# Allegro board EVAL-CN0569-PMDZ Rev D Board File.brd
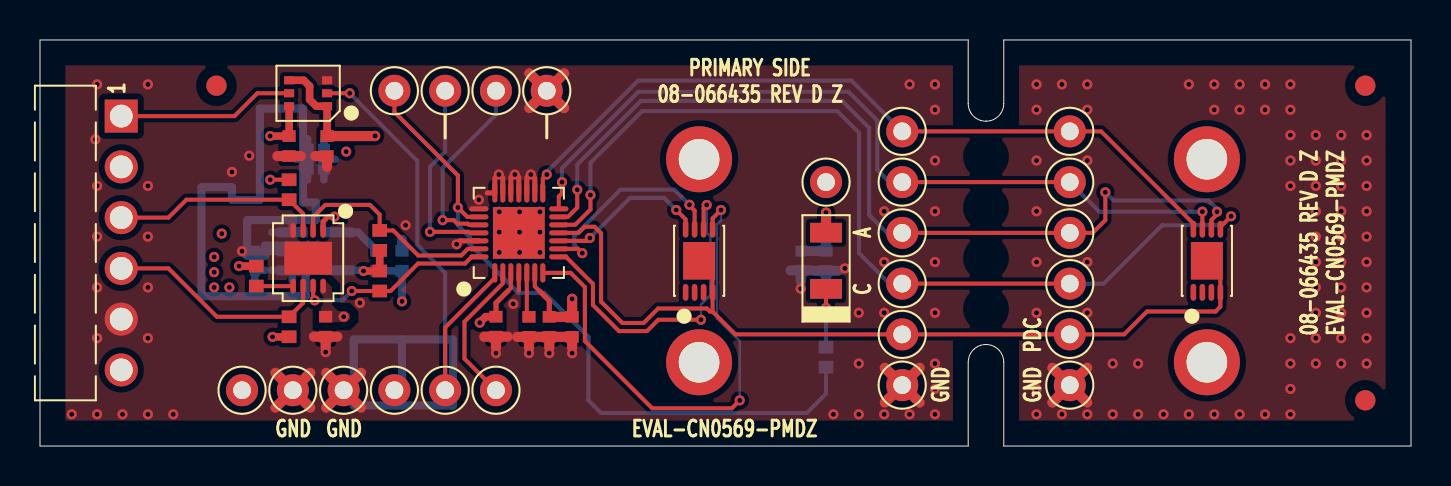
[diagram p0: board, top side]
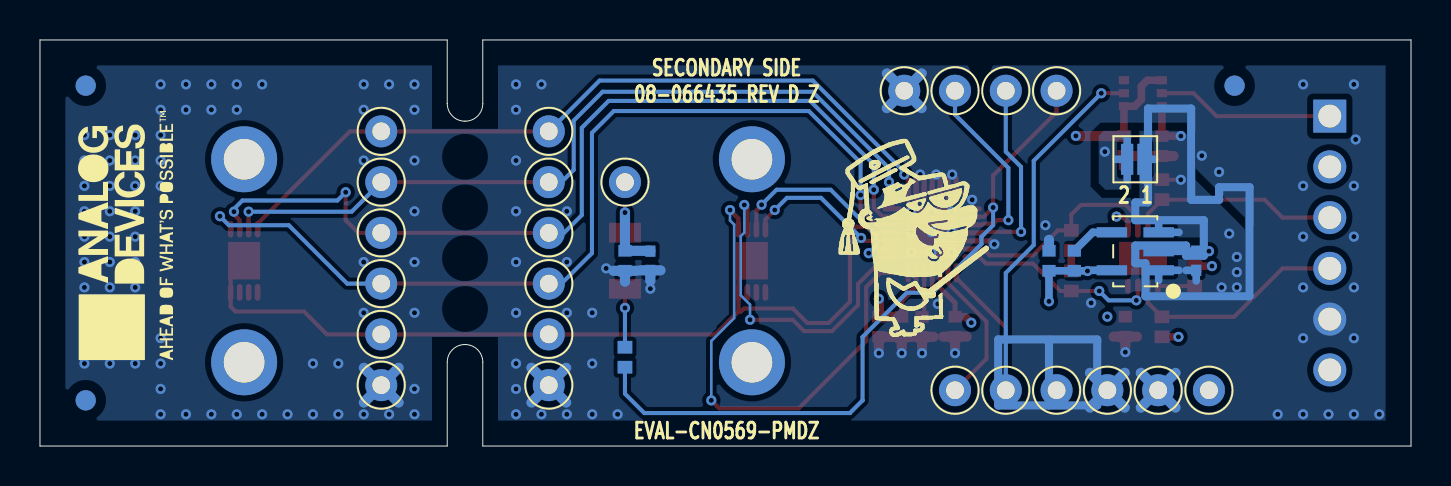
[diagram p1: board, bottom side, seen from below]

Outline 68.58 x 20.32 mm; copper layers: TOP, L2_GND, L3_PWR, BOTTOM. Coordinates in mm from the lower left corner of the outline.
Outline path: 0,20.32 0,0 46.43,0 46.43,4.19 arc(46.69,4.82) 47.32,5.08 47.32,5.08 arc(47.95,4.82) 48.21,4.19 48.21,0 68.58,0 68.58,20.32 48.21,20.32 48.21,17.14 arc(47.95,16.51) 47.32,16.25 47.31,16.25 arc(46.69,16.51) 46.43,17.14 46.43,20.32 0,20.32

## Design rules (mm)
constraint set DEFAULT: min track width 0.203

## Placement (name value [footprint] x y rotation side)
AGND  TP_VIA  [TPC63D35]  12.65 2.79 0 top
C1  1uF  [C0402]  24.46 5.96 270 top
C2  10uF  [C0402]  25.48 5.96 270 top
C3  0.1uF  [C0402]  26.62 5.96 270 top
C4  0.1uF  [C0402]  22.81 5.97 270 top
C5  0.1uF  [C0402]  12.46 15.01 270 top
C6  0.1uF  [C0402]  14.36 15.01 270 top
C7  0.01uF  [C0402]  14.29 5.97 270 top
C8  1uF  [C0402H22]  10.74 9.27 90 bottom
C9  0.01uF  [C0402]  16.84 9.27 90 bottom
C10  10uF  [C0402]  18.11 9.27 90 bottom
C11  2.2uF  [C0402H22]  38.05 9.27 270 bottom
C12  10uF  [C0402]  39.32 9.27 270 bottom
DGND  TP_VIA  [TPC63D35]  15.19 2.79 0 top
GND  TP_VIA  [TPC63D35]  25.35 17.78 0 top
GND1  TP_VIA  [TPC63D35]  43.13 3.05 0 top
GND2  TP_VIA  [TPC63D35]  51.51 3.05 0 top
IO0  TP_VIA  [TPC63D35]  20.27 2.79 0 top
IO1  TP_VIA  [TPC63D35]  22.81 2.79 0 top
IR_LED  SFH 4056  [LED1206H47]  39.32 9.27 90 top
JP1  -  [JPSLD02]  13.79 14.35 0 bottom
LED1  TP_VIA  [TPC63D35]  17.73 17.78 90 top
LED2  TP_VIA  [TPC63D35]  20.27 17.78 0 top
LED3  TP_VIA  [TPC63D35]  22.81 17.78 0 top
NOREF  -  []  0 0 0 top
NOREF#2  -  []  48.21 0 0 top
NOREF#3  -  [unnamed#2]  32.97 14.35 0 top
NOREF#4  -  []  276.81 307.21 0 top
NOREF#5  -  []  94.82 -25.4 270 top
NOREF#6  -  []  46.73 6.19 0 top
NOREF#7  -  []  -104.19 -156.34 0 top
NOREF#8  -  []  -104.19 -156.34 0 top
NOREF#9  -  []  0 0 0 top
NOREF#10  -  []  -43.23 214.5 0 top
NOREF#11  -  []  0 20.32 270 top
NOREF#12  -  []  13.79 14.61 0 top
NOREF#13  -  []  246.38 6.22 0 top
NOREF#14  -  []  0 20.32 0 top
NOREF#15  -  []  68.58 0 90 top
NOREF#16  -  [unnamed#2]  8.83 18.03 0 top
NOREF#17  -  []  46.43 0 0 top
NOREF#18  -  [unnamed#2]  66.29 18.03 0 top
NOREF#19  -  []  -104.19 -156.34 0 top
NOREF#20  -  [unnamed#2]  32.97 4.19 0 top
NOREF#21  -  []  -53.39 -14.1 0 top
NOREF#22  -  []  -66.09 170.05 0 top
NOREF#23  -  []  47.31 17.89 0 top
NOREF#24  -  []  0 0 0 top
NOREF#25  -  []  -104.19 -156.34 0 top
NOREF#26  -  [unnamed#2]  66.29 2.29 0 top
NOREF#27  -  []  68.58 20.32 180 top
NOREF#28  -  []  68.58 0 90 top
NOREF#29  -  [unnamed#2]  58.37 14.35 0 top
NOREF#30  -  []  68.58 0 0 top
NOREF#31  -  [unnamed#2]  58.37 4.19 0 top
NOREF#32  -  []  0 20.32 0 top
NOREF#33  -  []  72.9 10.16 90 bottom
NOREF#34  -  [unnamed#2]  66.29 18.03 180 bottom
NOREF#35  -  [unnamed#2]  8.83 18.03 180 bottom
NOREF#36  -  [unnamed#2]  66.29 2.29 180 bottom
P1  TSW-106-25-F-S-RA  [CNHDRRA1X6H122]  4.06 16.51 270 top
PD5  TP_VIA  [TPC63D35]  43.13 8.13 0 top
PD6  TP_VIA  [TPC63D35]  43.13 10.67 0 top
PD7  TP_VIA  [TPC63D35]  43.13 13.21 0 top
PD8  TP_VIA  [TPC63D35]  43.13 15.75 0 top
PDC  TP_VIA  [TPC63D35]  43.13 5.59 0 top
PDC2  TP_VIA  [TPC63D35]  51.51 5.59 0 top
R1  0  [R0402]  39.32 4.44 270 bottom
R2  10K  [R0402]  12.46 5.97 90 top
R3  10K  [R0402]  12.46 12.83 270 top
R4  10K  [R0402]  10.82 8.5 270 top
R5  10K  [R0402]  16.99 8.26 270 top
R6  10K  [R0402]  16.99 10.29 90 top
U1  ADPD2140BCPZN-R7  [DFN8_2X3_PAD1_59X1_89]  32.97 9.27 0 top
U2  ADPD2140BCPZN-R7  [DFN8_2X3_PAD1_59X1_89]  58.37 9.27 0 top
U3  ADPD1080BCPZ  [QFN28_4X4_PAD2_6X2_6]  23.95 10.67 0 top
U4  ADG3301BKSZ  [SC70-6]  13.41 17.65 90 top
U5  LTC4313IDD-3#PBF  [DFN8_3X3_PAD2_38X1_65]  13.41 9.4 180 top
U6  LT1761ES5-1.8#TRPBF  [TSOT-5]  13.79 9.74 90 bottom
UNK1V8  TP_VIA  [TPC63D35]  17.73 2.79 0 top
VCC  TP_VIA  [TPC63D35]  10.11 2.79 0 top
VLED  TP_VIA  [TPC63D35]  39.32 13.21 0 top
XL2  TP_VIA  [TPC63D35]  51.51 10.67 0 top
XR2  TP_VIA  [TPC63D35]  51.51 8.13 0 top
YB2  TP_VIA  [TPC63D35]  51.51 13.21 0 top
YT2  TP_VIA  [TPC63D35]  51.51 15.75 0 top

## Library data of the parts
AGND DGND GND GND1 GND2 IO0 IO1 LED1-LED3 PD5-PD8 PDC PDC2 UNK1V8 VCC VLED XL2 XR2 YB2 YT2 = NCTESTPAD: Tolerance: N/A; User Part Number: UPN; alternate symbols: (); part number: NCTESTPAD_TH-TP_VIA,E012149,TPC63D35; tolerance: N/A
C1 = CAP: User Part Number: UPN; Tolerance: 20; alternate symbols: (C0402L); part number: CAP_SM-1UF,16V,20,E020695,C0402; tolerance: 20
C2 C10 C12 = CAP: User Part Number: UPN; Tolerance: 20; alternate symbols: (C0402L); part number: CAP_SM-10UF,6.3V,20,E032074,C0402; tolerance: 20
C3-C6 = CAP: User Part Number: UPN; Tolerance: 10; alternate symbols: (C0402L_ALT,C0402L); part number: CAP_SM-0.1UF,25V,10,E025798,C0402; tolerance: 10
C7 C9 = CAP: User Part Number: UPN; Tolerance: 10; alternate symbols: (C0402L); part number: CAP_SM-0.01UF,50V,10,E021852,C0402; tolerance: 10
C8 = CAP: Tolerance: 20; User Part Number: UPN; alternate symbols: (); part number: CAP_SM-1UF,25V,20,E028570,C0402H22; tolerance: 20
C11 = CAP: Tolerance: 10; User Part Number: UPN; alternate symbols: (); part number: CAP_SM-2.2UF,10V,10,E027484,C0402H22; tolerance: 10
IR_LED = DIOLED: Tolerance: N/A; User Part Number: UPN; alternate symbols: (); part number: DIOLED_SM-SFH 4056,1.6V,N/A,E031632,LED1206H47; tolerance: N/A
JP1 = NC2P: User Part Number: UPN; Tolerance: N/A; alternate symbols: (); part number: NC2P_SM-JPSLD02,E006230,JPSLD02; tolerance: N/A
P1 = CN6P: User Part Number: UPN; Tolerance: N/A; alternate symbols: (); part number: CN6P_TH-TSW-106-25-F-S-RA,E018547,CNHDRRA1X6H122; tolerance: N/A
R1 = RES: User Part Number: UPN; Tolerance: JUMPER; alternate symbols: (R0402L,R0402L_ALT); part number: RES_SM-0,E003438,1/10W,JUMPER,R0402; tolerance: JUMPER
R2-R6 = RES: User Part Number: UPN; Tolerance: 1; alternate symbols: (R0402L,R0402L_ALT); part number: RES_SM-10K,E003751,1/10W,1,R0402; tolerance: 1
U1 U2 = ADPD2140: Tolerance: N/A; User Part Number: UPN; alternate symbols: (); part number: ADPD2140_SM-ADPD2140BCPZN-R7,E032570,DFN8_2X3_PAD1_59X1_89; tolerance: N/A
U3 = ADPD1080_V2: Tolerance: N/A; User Part Number: UPN; alternate symbols: (); part number: ADPD1080_V2_SM-ADPD1080BCPZ,E030400,QFN28_4X4_PAD2_6X2_6; tolerance: N/A
U4 = ADG3301: Tolerance: N/A; User Part Number: UPN; alternate symbols: (); part number: ADG3301_SM-ADG3301BKSZ,E010847,SC70-6; tolerance: N/A
U5 = LINLTC4313: User Part Number: UPN; Tolerance: N/A; alternate symbols: (); part number: LINLTC4313_SM-LTC4313IDD-3#PBF,E034872,DFN8_3X3_PAD2_38X1_65; tolerance: N/A
U6 = LINLT1761_X: User Part Number: UPN; Tolerance: N/A; alternate symbols: (); part number: LINLT1761_X_SM-LT1761ES5-1.8#TRPBF,E015635,TSOT-5; tolerance: N/A

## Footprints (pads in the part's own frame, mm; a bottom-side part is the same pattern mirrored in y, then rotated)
C0402
  rect 0.584x0.66 smd: 1(-0.5,0) 2(0.5,0)
C0402H22
  rect 0.559x0.508 smd: 1(-0.479,0) 2(0.479,0)
CNHDRRA1X6H122
  rect 1.651x1.651 hole 1.143: 1(0,0)
  round 1.651 hole 1.143: 2(2.54,0) 3(5.08,0) 4(7.62,0) 5(10.16,0) 6(12.7,0)
DFN8_2X3_PAD1_59X1_89
  oval 0.279x0.838 smd: 1(-0.675,-1.581) 2(-0.225,-1.581) 3(0.225,-1.581) 4(0.675,-1.581) 5(0.675,1.581) 6(0.225,1.581) 7(-0.225,1.581) 8(-0.675,1.581)
  rect 1.6x1.88 smd: PAD(0,0)
DFN8_3X3_PAD2_38X1_65
  oval 0.279x0.737 smd: 1(-0.75,-1.393) 2(-0.25,-1.393) 3(0.25,-1.393) 4(0.75,-1.393) 5(0.75,1.393) 6(0.25,1.393) 7(-0.25,1.393) 8(-0.75,1.393)
  rect 2.388x1.651 smd: PAD(0,0)
JPSLD02
  rect 0.61x1.549 smd: 1(-0.406,0) 2(0.406,0)
LED1206H47
  rect 0.991x1.6 smd: A(1.405,0) C(-1.405,0)
QFN28_4X4_PAD2_6X2_6
  oval 0.254x0.965 smd: 1(-1.2,-2) 2(-0.8,-2) 3(-0.4,-2) 4(0,-2) 5(0.4,-2) 6(0.8,-2) 7(1.2,-2) 15(1.2,2) 16(0.8,2) 17(0.4,2) 18(0,2) 19(-0.4,2) 20(-0.8,2) 21(-1.2,2)
  oval 0.965x0.254 smd: 8(2,-1.2) 9(2,-0.8) 10(2,-0.4) 11(2,0) 12(2,0.4) 13(2,0.8) 14(2,1.2) 22(-2,1.2) 23(-2,0.8) 24(-2,0.4) 25(-2,0) 26(-2,-0.4) 27(-2,-0.8) 28(-2,-1.2)
  rect 2.591x2.591 smd: PAD(0,0)
R0402
  rect 0.635x0.737 smd: 1(-0.5,0) 2(0.5,0)
SC70-6
  rect 0.406x0.508 smd: 1(-0.65,-0.95) 2(0,-0.95) 3(0.65,-0.95) 4(0.65,0.95) 5(0,0.95) 6(-0.65,0.95)
TPC63D35
  round 1.6 hole 0.889: 1(0,0)
TSOT-5
  rect 0.508x1.524 smd: 1(-0.95,-1.17) 2(0,-1.17) 3(0.95,-1.17) 4(0.95,1.17) 5(-0.95,1.17)
unnamed#2
  round 3.302 hole 2.032 unplated: (0,0)

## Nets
1V8_SCL: R6.2(N2) U3.27 U5.2
1V8_SDA: R5.2(N2) U3.28 U5.7
1V8_VDD: C2.1 C3.1 C4.1 C6.1 C9.1 C10.1 R4.1 R5.1 R6.1 U3.3 U3.6 U4.1 U4.4 U6.5 UNK1V8.1
GND: AGND.1(N1) C1.2(N2) C2.2(N2) C3.2(N2) C4.2(N2) C5.2(N2) C6.2(N2) C7.2(N2) C8.2(N2) C10.2(N2) C11.2(N2) C12.2(N2) DGND.1(N1) GND.1(N1) GND1.1(N1) GND2.1(N1) P1.5 U3.4 U3.16 U3.17 U3.18 U3.19 U3.20 U3.21 U3.22 U3.26 U3.PAD U4.3 U5.4 U5.PAD U6.2
IO0: IO0.1(N1) U3.1 U4.2
PD5: PD5.1(N1) U2.5 U3.12 XR2.1(N1)
PD6: PD6.1(N1) U2.6 U3.13 XL2.1(N1)
PD7: PD7.1(N1) U2.7 U3.14 YB2.1(N1)
PD8: PD8.1(N1) U2.8(YT) U3.15 YT2.1(N1)
PDC: PDC.1(N1) PDC2.1(N1) U1.4 U1.PAD U2.4 U2.PAD U3.11
PMOD_VCC: C5.1 C7.1 C8.1 JP1.1 P1.6(N6) R2.1 R3.1 U4.6 U5.1 U5.8(VCC) U6.1 U6.3(SHDN_N) VCC.1(N1)
UNNAMED_2_ADPD1080V2_I3_GPIO1: IO1.1(N1) U3.2
UNNAMED_2_ADPD1080V2_I3_LEDX1: LED1.1(N1) R1.2(N2) U3.23
UNNAMED_2_ADPD1080V2_I3_LEDX2: LED2.1(N1) U3.25
UNNAMED_2_ADPD1080V2_I3_LEDX3: LED3.1(N1) U3.24
UNNAMED_2_ADPD1080V2_I3_PD1: U1.5 U3.7
UNNAMED_2_ADPD1080V2_I3_PD2: U1.6 U3.8
UNNAMED_2_ADPD1080V2_I3_PD3: U1.7 U3.9
UNNAMED_2_ADPD1080V2_I3_PD4: U1.8(YT) U3.10
UNNAMED_2_ADPD1080V2_I3_VREF: C1.1 U3.5(VREF)
UNNAMED_2_DIOLED_I122_N: IR_LED.C R1.1
UNNAMED_3_ADG3301_I41_Y: P1.1 U4.5(Y)
UNNAMED_3_CAP_I23_N2: C9.2(N2) U6.4
UNNAMED_3_LINLTC4313_I1_READY: R4.2(N2) U5.5
UNNAMED_3_LINLTC4313_I1_SCLIN: P1.3 R3.2(N2) U5.3
UNNAMED_3_LINLTC4313_I1_SDAIN: P1.4 R2.2(N2) U5.6
VLED: C11.1 C12.1 IR_LED.A(P) JP1.2(N2) VLED.1(N1)

Pads without a net: P1 2; U1 1 2 3; U2 1 2 3

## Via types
v1: diameter 0.508, hole 0.254, TOP to BOTTOM, 174 vias

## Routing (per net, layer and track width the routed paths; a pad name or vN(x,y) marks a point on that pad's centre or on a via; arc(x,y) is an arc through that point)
1V8_SCL: length 10.9
  TOP w0.203: U5.2 13.66,11.45 14.27,12.06 16.51,12.06 16.99,11.58 R6.2 17.67,10.79 18.92,9.54 21.07,9.54 21.4,9.87 U3.27
1V8_SDA: length 9.9
  TOP w0.203: v1(15.6,7.76) R5.2 17.54,7.76 18.91,9.13 21.26,9.13 21.6,9.47 U3.28 ; v1(13.74,7.29) 13.66,7.37 U5.7
  BOTTOM w0.203: v1(13.74,7.29) 15.13,7.29 v1(15.6,7.76)
1V8_VDD: length 30.2
  TOP w0.203: 24.99,7.75 24.75,7.99 U3.6 ; 23.42,7.77 23.55,7.91 U3.3
  TOP w0.254: C2.1 25.48,7.26 24.99,7.75 ; 23.42,7.77 22.81,7.16 C4.1
  TOP w0.381: R4.1 v1(9.96,9) ; C4.1 22.3,6.47 v1(22,6.17) ; C6.1 U4.1 13.82,17 13.49,17.34 13.49,18.01 13.19,18.3 U4.4 ; v1(16.18,8.76) R5.1 R6.1
  TOP w0.508: C6.1 16.76,15.51 v1(16.76,15.52) ; v1(26.62,7.37) C3.1 C2.1
  L3_PWR w0.508: 16.76,9.85 v1(16.76,15.52)
  L3_PWR w0.711: 18.6,3.66 UNK1V8.1 16.86,3.66
  BOTTOM w0.381: U6.5 16.15,8.8 v1(16.18,8.76) 16.2,8.77 C9.1 C10.1 v1(18.11,7.24)
GND: length 114.4
  TOP w0.203: 23.95,7.77 U3.4
  TOP w0.254: v1(20.84,10.1) 21.01,10.27 U3.26 ; U3.18 23.95,13.46 ; 22.37,12.67 U3.21 22.75,13.4 ; U3.16 24.75,13.42 ; 23.55,13.46 U3.19 ; U3.20 23.15,13.42 ; U3.17 24.35,13.44
  TOP w0.508: GND.1 26.22,18.65 ; GND.1 24.48,16.91 ; GND.1 26.22,16.91 ; GND.1 24.48,18.65 ; AGND.1 13.52,1.92 ; AGND.1 11.78,3.66 ; AGND.1 13.52,3.66 ; AGND.1 11.78,1.92 ; GND2.1 52.38,3.92 ; GND2.1 52.38,2.18 ; GND2.1 50.64,2.18 ; GND2.1 50.64,3.92 ; 14.32,3.66 DGND.1 ; DGND.1 16.06,3.66 ; DGND.1 14.32,1.92 ; DGND.1 16.06,1.92 ; 42.26,2.18 GND1.1 ; GND1.1 44,3.92 ; GND1.1 42.26,3.92 ; GND1.1 44,2.18 ; 13.78,14.51 C6.2 14.36,13.96 ; 24.46,4.92 C1.2 ; C1.2 23.88,5.46 ; C1.2 C2.2 ; 11.88,14.51 C5.2 13.05,14.51 ; C7.2 14.88,5.47 ; C7.2 13.71,5.47 ; C7.2 14.29,4.93 ; 25.48,4.92 C2.2 ; C2.2 C3.2 26.62,4.92 ; C4.2 23.39,5.47 ; C4.2 22.81,4.93 ; C4.2 22.22,5.47
  L2_GND w0.711: 50.64,3.92 GND2.1 ; GND2.1 52.38,3.92 ; GND2.1 52.38,2.18 ; GND2.1 50.64,2.18 ; 24.48,18.65 GND.1 ; GND.1 26.22,18.65 ; GND.1 24.48,16.91 ; GND.1 26.22,16.91 ; 14.32,3.66 DGND.1 ; DGND.1 16.06,1.92 ; DGND.1 14.32,1.92 ; DGND.1 16.06,3.66 ; GND1.1 44,3.92 ; GND1.1 42.26,2.18 ; GND1.1 42.26,3.92 ; GND1.1 44,2.18 ; 11.78,3.66 AGND.1 ; AGND.1 11.78,1.92 ; AGND.1 13.52,3.66 ; AGND.1 13.52,1.92
  L3_PWR w0.711: AGND.1 13.52,3.66 ; AGND.1 11.78,3.66 ; AGND.1 13.52,1.92 ; AGND.1 11.78,1.92 ; GND2.1 52.38,2.18 ; GND2.1 52.38,3.92 ; GND2.1 50.64,3.92 ; GND2.1 50.64,2.18 ; 42.26,2.18 GND1.1 ; GND1.1 44,2.18 ; GND1.1 42.26,3.92 ; GND1.1 44,3.92 ; 14.32,3.66 DGND.1 14.32,1.92
  BOTTOM w0.381: U6.2 11.4,9.74 11.39,9.75 C8.2 v1(10.1,9.75)
  BOTTOM w0.508: AGND.1 13.52,1.92 ; AGND.1 13.52,3.66 ; AGND.1 11.78,1.92 ; AGND.1 11.78,3.66 ; 14.32,1.92 DGND.1 ; DGND.1 16.06,1.92 ; DGND.1 14.32,3.66 ; DGND.1 16.06,3.66 ; 50.64,2.18 GND2.1 ; GND2.1 52.38,3.92 ; GND2.1 50.64,3.92 ; GND2.1 52.38,2.18 ; 42.26,3.92 GND1.1 ; GND1.1 44,2.18 ; GND1.1 42.26,2.18 ; GND1.1 44,3.92 ; 38.73,8.77 C12.2 ; C12.2 39.32,8.22 ; C12.2 39.9,8.77 ; C10.2 18.11,10.32 ; GND.1 26.22,18.65 ; GND.1 26.22,16.91 ; GND.1 24.48,18.65 ; GND.1 24.48,16.91 ; C11.2 38.56,8.79 ; C11.2 38.05,8.26 ; C11.2 37.54,8.79
  vias: v1(1.59,1.59) v1(2.77,15.34) v1(2.86,18.1) v1(2.86,13.02) v1(2.86,10.48) v1(2.86,7.94) v1(2.86,5.4) v1(2.86,1.59) v1(4.13,1.59) v1(5.4,18.1) v1(5.4,13.02) v1(5.4,10.48) v1(5.4,7.94) v1(5.4,5.4) v1(5.4,1.59) v1(6.67,1.59) v1(9.6,13.71) v1(10.46,14.53) v1(14.29,4.7) v1(16,7.16) v1(18.29,11.05) v1(21.95,12.32) v1(22.81,4.65) v1(22.95,13.59) v1(22.97,11.72) v1(22.97,10.71) v1(22.97,9.69) v1(23.67,7.11) v1(23.75,13.59) v1(23.99,11.72) v1(23.99,10.71) v1(23.99,9.69) v1(24.46,4.65) v1(24.55,13.59) v1(25.01,11.72) v1(25.01,10.71) v1(25.01,9.69) v1(25.48,4.65) v1(26.62,4.65) v1(38.05,7.87) v1(39.69,1.59) v1(40.26,8.89) v1(40.96,6.67) v1(40.96,4.13) v1(40.96,1.59) v1(42.23,11.75) v1(42.23,9.21) v1(42.23,6.67) v1(42.23,1.59) v1(43.5,18.1) v1(43.5,1.59) v1(44.77,18.1) v1(44.77,16.83) v1(44.77,14.29) v1(44.77,11.75) v1(44.77,9.21) v1(44.77,6.67) v1(44.77,4.13) v1(44.77,2.86) v1(44.77,1.59) v1(49.85,18.1) v1(49.85,16.83) v1(49.85,14.29) v1(49.85,11.75) v1(49.85,9.21) v1(49.85,6.67) v1(49.85,2.86) v1(49.85,1.59) v1(51.12,18.1) v1(51.12,1.59) v1(52.39,18.1) v1(52.39,16.83) v1(52.39,14.29) v1(52.39,9.21) v1(52.39,6.67) v1(52.39,1.59) v1(53.66,4.13) v1(53.66,1.59) v1(54.93,4.13) v1(54.93,1.59) v1(56.2,1.59) v1(57.47,18.1) v1(57.47,1.59) v1(58.74,18.1) v1(58.74,16.83) v1(58.74,1.59) v1(60.01,18.1) v1(60.01,16.83) v1(60.01,1.59) v1(61.28,18.1) v1(61.28,16.83) v1(61.28,1.59) v1(62.55,18.1) v1(62.55,16.83) v1(62.55,15.56) v1(62.55,14.29) v1(62.55,13.02) v1(62.55,5.4) v1(62.55,4.13) v1(62.55,2.86) v1(62.55,1.59) v1(63.82,15.56) v1(63.82,14.29) v1(63.82,13.02) v1(63.82,11.75) v1(63.82,10.48) v1(63.82,9.21) v1(63.82,7.94) v1(63.82,6.67) v1(63.82,5.4) v1(63.82,4.13) v1(65.09,15.56) v1(65.09,14.29) v1(65.09,13.02) v1(65.09,11.75) v1(65.09,10.48) v1(65.09,9.21) v1(65.09,7.94) v1(65.09,6.67) v1(65.09,5.4) v1(65.09,4.13) v1(66.36,15.56) v1(66.36,14.29) v1(66.36,13.02) v1(66.36,11.75) v1(66.36,10.48) v1(66.36,9.21) v1(66.36,7.94) v1(66.36,6.67) v1(66.36,5.4) v1(66.36,4.13)
IO0: length 24.9
  TOP w0.203: IO0.1 20.27,5.93 22.75,8.41 U3.1 ; U4.2 v1(15.49,17.65)
  BOTTOM w0.203: v1(15.49,17.65) 18.87,14.27 18.87,10.06 20.27,8.66 IO0.1
PD5: length 46.7
  TOP w0.203: v1(27.53,12.56) 27.53,11.84 26.77,11.07 26.32,11.07 26.32,11.07 U3.12 ; PD5.1 XR2.1 ; v1(59.58,11.5) 59.04,10.97 U2.5
  BOTTOM w0.203: XR2.1 53.21,8.13 56.13,11.05 59.13,11.05 v1(59.58,11.5) ; v1(27.53,12.56) 27.53,14.17 30.12,16.76 39.88,16.76 40.97,15.67 40.97,9.65 42.49,8.13 PD5.1
PD6: length 45
  TOP w0.203: v1(53.29,12.7) 53.29,11.3 52.65,10.67 XL2.1 PD6.1 ; U3.13 26.41,11.47 26.87,11.93 v1(26.87,12.83) ; U2.6 58.59,11.09 58.6,11.09 58.6,11.31 58.88,11.59 v1(58.88,11.73)
  BOTTOM w0.203: v1(53.29,12.7) 53.7,12.29 58.45,12.29 58.88,11.86 v1(58.88,11.73) ; v1(26.87,12.83) 26.87,14.09 30.05,17.27 40.13,17.27 41.48,15.93 41.48,11.56 42.37,10.67 PD6.1
PD7: length 40.5
  TOP w0.203: v1(58.14,11.73) U2.7 ; PD7.1 YB2.1 ; U3.14 25.95,12.49 26.11,12.65 v1(26.11,13.21)
  BOTTOM w0.203: v1(26.11,13.21) 26.11,13.9 29.94,17.73 40.44,17.73 41.88,16.28 41.88,13.82 42.49,13.21 PD7.1 ; YB2.1 52.99,11.73 v1(58.14,11.73)
PD8: length 38.6
  TOP w0.203: PD8.1 YT2.1 53.08,15.75 57.69,11.13 U2.8 ; U3.15 25.15,13.39 v1(25.35,13.59)
  BOTTOM w0.203: v1(25.35,13.59) 25.35,13.71 29.92,18.29 40.59,18.29 PD8.1
PDC: length 44
  TOP w0.203: 33.64,6.73 34.79,5.59 PDC.1 PDC2.1 54.23,5.59 55.37,6.73 58.8,6.73 59.04,6.98 U2.4 59.04,8.6 U2.PAD ; 33.64,6.73 U1.4 33.64,8.6 U1.PAD ; 33.64,6.73 33.51,6.73 33.36,6.88 30.92,6.88 30.19,6.16 29.13,6.16 28.07,7.22 28.07,10.64 27.74,10.97 27.24,10.97 26.94,10.67 U3.11
PMOD_VCC: length 16.7
  TOP w0.203: R3.1 v1(11.52,13.33)
  TOP w0.254: v1(14.73,11.48) 14.42,11.48 14.16,11.23 U5.1
  TOP w0.381: U4.6 C5.1 v1(11.51,15.51) ; R2.1 12.45,5.46 v1(11.63,5.46)
  L3_PWR w0.711: 8.95,2.79 VCC.1 10.11,3.95 ; 2.88,3.81 P1.6 5.25,3.81
  BOTTOM w0.381: 11.25,8.79 C8.1 10.74,8.26 ; JP1.1 13.39,15.38 ; JP1.1 12.83,14.35 ; JP1.1 13.39,13.32 ; 11.61,10.69 U6.3 12.62,11.2 ; 11.61,8.8 U6.1 12.62,8.29
  vias: v1(8.71,9.46) v1(8.71,8.7) v1(8.71,7.94) v1(9.09,10.63) v1(9.47,7.94) v1(15.19,6.47)
UNNAMED_2_ADPD1080V2_I3_GPIO1: length 7.3
  TOP w0.203: IO1.1 21.23,4.37 21.23,6.22 23.15,8.14 U3.2
UNNAMED_2_ADPD1080V2_I3_LEDX1: length 35.4
  TOP w0.203: U3.23 21.37,11.47 v1(20.9,11.94) 20.9,13.53 20.9,13.54 20.9,13.55 17.73,16.71 LED1.1
  BOTTOM w0.203: R1.2 39.32,2.62 38.35,1.65 28.07,1.65 28.06,1.66 27.44,2.28 27.43,2.29 27.43,2.3 27.43,5.45 27.43,5.46 25.22,7.67 25.21,7.67 23.94,7.67 23.93,7.67 23.92,7.68 21.5,10.1 21.49,10.11 21.49,10.12 21.49,10.45 21.49,10.46 21.48,10.47 20.9,11.05 v1(20.9,11.94)
UNNAMED_2_ADPD1080V2_I3_LEDX2: length 9.8
  TOP w0.203: v1(19.51,10.72) 21.42,10.72 21.47,10.67 U3.25
  BOTTOM w0.203: v1(19.51,10.72) 19.51,13.97 20.27,14.73 LED2.1
UNNAMED_2_ADPD1080V2_I3_LEDX3: length 9.5
  TOP w0.203: U3.24 21.46,11.07 21.4,11.12 20.88,11.12 20.7,11.3 v1(20.14,11.3)
  BOTTOM w0.203: v1(20.14,11.3) 20.14,13.92 22.81,16.59 LED3.1
UNNAMED_2_ADPD1080V2_I3_PD1: length 25.6
  TOP w0.203: v1(35,2.28) 34.61,1.89 30.62,1.89 27.25,5.26 27.25,7.95 26.54,8.67 U3.7 ; v1(34.06,11.81) 33.64,11.39 U1.5
  BOTTOM w0.127: v1(34.06,11.81) 34.06,11.29 33.86,11.08 33.86,6.4 35,5.26 v1(35,2.28)
UNNAMED_2_ADPD1080V2_I3_PD2: length 16.8
  TOP w0.203: U3.8 26.31,9.47 27.66,8.11 27.66,7.05 28.96,5.75 30.36,5.75 30.93,6.32 v1(33.06,6.32) ; v1(33.35,12.06) 33.19,11.91 U1.6
  BOTTOM w0.127: v1(33.35,12.06) 33.35,10.68 33.53,10.5 33.53,7.54 33.06,7.08 v1(33.06,6.32)
UNNAMED_2_ADPD1080V2_I3_PD3: length 10.7
  TOP w0.203: U3.9 26.91,9.87 v1(27.13,9.65) ; U1.7 32.74,11.78 32.49,12.04 v1(32.49,12.07)
  BOTTOM w0.203: v1(32.49,12.07) 31.73,12.83 29.03,12.83 26.73,10.53 26.73,10.05 v1(27.13,9.65)
UNNAMED_2_ADPD1080V2_I3_PD4: length 8.2
  TOP w0.203: U3.10 27.36,10.27 v1(27.51,10.41) ; v1(31.83,11.81) 32.29,11.34 U1.8
  BOTTOM w0.203: v1(31.83,11.81) 31.22,12.42 29.51,12.42 v1(27.51,10.41)
UNNAMED_2_ADPD1080V2_I3_VREF: length 2.2
  TOP w0.203: C1.1 24.35,6.57 U3.5
UNNAMED_2_DIOLED_I122_N: length 2.9
  TOP w0.203: IR_LED.C v1(39.32,6.91)
  BOTTOM w0.203: R1.1 v1(39.32,6.91)
UNNAMED_3_ADG3301_I41_Y: length 8.9
  TOP w0.203: P1.1 9.73,16.51 10.87,17.65 U4.5
UNNAMED_3_CAP_I23_N2: length 2.3
  BOTTOM w0.381: U6.4 15.92,10.69 C9.2
UNNAMED_3_LINLTC4313_I1_READY: length 1.8
  TOP w0.203: R4.2 U5.5
UNNAMED_3_LINLTC4313_I1_SCLIN: length 10.6
  TOP w0.203: P1.3 6.43,11.43 7.32,12.33 R3.2 13.16,11.63 U5.3
UNNAMED_3_LINLTC4313_I1_SDAIN: length 11.2
  TOP w0.203: P1.4 6.43,8.89 8.85,6.47 R2.2 13.16,7.17 U5.6
VLED: length 11.4
  TOP w0.508: IR_LED.A v1(39.32,11.68)
  L3_PWR w0.711: VLED.1 39.32,14.36 ; VLED.1 40.48,13.21 ; VLED.1 39.32,12.05 ; VLED.1 38.16,13.21
  BOTTOM w0.381: JP1.2 14.76,14.35 ; JP1.2 14.2,15.38 ; JP1.2 14.2,13.32
  BOTTOM w0.508: v1(39.32,11.68) C12.1 38.07,9.77 C11.1
  vias: v1(15.32,14.73)

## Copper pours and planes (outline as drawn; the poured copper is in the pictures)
1V8_VDD on L3_PWR: 9.68,10.59 16.64,10.59 16.64,10.29 16.7,10.14 16.84,10.08 17.73,10.08 17.73,7.82 27.43,7.82 27.43,6.73 27.49,6.59 27.63,6.53 29.34,6.53 29.34,1.98 25.1,1.98 25.1,1.96 16.13,1.96 16.13,1.98 15.9,1.98 15.9,6.4 15.95,6.4 15.95,8.58 9.68,8.58
GND on TOP: 48.97,19.05 67.31,19.05 67.31,1.27 48.97,1.27 48.97,5.46 45.67,5.46 45.67,1.27 1.27,1.27 1.27,19.05 45.67,19.05 45.67,15.87 48.97,15.87 ; 5 cut-outs
GND on BOTTOM: 48.97,19.05 67.31,19.05 67.31,1.27 48.97,1.27 48.97,5.46 45.67,5.46 45.67,1.27 1.27,1.27 1.27,19.05 45.67,19.05 45.67,15.87 48.97,15.87 ; 3 cut-outs
GND on L2_GND: 48.97,19.05 67.31,19.05 67.31,1.27 48.97,1.27 48.97,5.46 45.67,5.46 45.67,1.27 1.27,1.27 1.27,19.05 45.67,19.05 45.67,15.87 48.97,15.87
GND on L3_PWR: 48.97,19.05 67.31,19.05 67.31,1.27 48.97,1.27 48.97,5.46 45.67,5.46 45.67,1.27 1.27,1.27 1.27,2.21 7.82,2.21 7.97,2.27 8.03,2.41 8.03,3.22 8.8,3.99 15.49,3.99 15.49,1.78 15.55,1.63 15.7,1.57 29.54,1.57 29.68,1.63 29.74,1.78 29.74,6.73 29.68,6.87 29.54,6.93 27.84,6.93 27.84,8.43 18.11,8.43 18.11,10.49 17.04,10.49 17.04,13.64 18.24,13.64 18.38,13.7 18.44,13.84 18.44,14.27 21.03,14.27 21.17,14.33 21.23,14.48 21.23,15.29 36.83,15.29 36.83,9.45 42.06,9.45 42.06,19.05 45.67,19.05 45.67,15.87 48.97,15.87
PMOD_VCC on TOP: 14.05,8.26 14.3,8.26 14.61,7.95 14.61,7.06 14.91,6.76 15.34,6.76 15.52,6.58 15.52,6.38 15.34,6.2 14.05,6.2
PMOD_VCC on BOTTOM: 11.4,15.77 13.59,15.77 13.59,11.51 13.41,11.51 13.41,10.44 10.16,10.44 10.16,9.52 10.22,9.38 10.36,9.32 11.25,9.32 11.4,9.38 11.46,9.52 11.46,9.83 13.59,9.83 13.59,9.35 13.28,9.35 13.14,9.29 13.08,9.14 13.08,7.7 8.28,7.7 8.28,10.82 11.2,13.74 11.2,15.57
PMOD_VCC on L3_PWR: 1.27,19.05 13.77,19.05 13.77,14.22 14.61,13.39 16.64,13.39 16.64,11 9.47,11 9.33,10.94 9.27,10.79 9.27,8.38 9.33,8.24 9.47,8.18 15.44,8.18 15.44,4.39 10.87,4.39 10.87,2.34 1.27,2.34
VLED on BOTTOM: 14,15.77 14,12.83 15.29,12.83 15.62,13.16 15.62,15.52 15.37,15.77
VLED on L3_PWR: 18.69,19.05 39.7,19.05 39.7,19.05 41.66,19.05 41.66,9.85 37.24,9.85 37.24,15.37 20.83,15.37 20.83,14.68 18.24,14.68 18.09,14.62 18.03,14.48 18.03,14.05 16.92,14.05 16.92,14.12 15.01,14.12 14.38,14.76 14.38,19.05 16.92,19.05 16.92,19.05 18.69,19.05

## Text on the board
Ref Des/Assembly Bottom: 1 | 2
Ref Des/Silkscreen Bottom: 1 | 2 | EVAL-CN0569-PMDZ
User.Comments: SMOOTHEN EDGES AND FREE FROM BURS AFTER DEPANELIZATION PROCESS. | 5.    BOARDS TO BE SHIPPED SINGULATED AFTER ASSEMBLY PROCESS.
Ref Des/Assembly Top: A | C
Ref Des/Silkscreen Top: GND | EVAL-CN0569-PMDZ | 1 | A | C | PDC | 08-066435 REV D Z
PAGE_OUTLINE: B | C | D | CHANGES AS PER ECR-102535 | CHANGES AS PER ECR-105094 | CHANGES AS PER ECR-105685 | 28APR21 | 18OCT21 | 25NOV21 | A. UY | EVAL-CN0569-PMDZ
DIMENSION: (REF) | (2 PLACES) | DIA MAX | (4 PLACES)
User.12: SEE NOTE #1 | 1. ADD SOLDER BLOB AT PINS 1 & 2 OF JP1. | ASSEMBLY NOTES 2:
User.15: PANEL TO BE SUBJECTED TO CUSTOMER'S APPROVAL. | 15.    BOARDS TO BE SHIPPED IN ARRAY AND KEEP INTACT. | PANELED SOLDER PASTE STENCIL SHOULD BE SENT TO THE CUSTOMER.
User.17: 08-      -07 | L2 GND
User.18: 08-      -08 | L3 PWR
User.45: FIGURE | SIZE | 10.0 | 35.0 | 45.0 | 80.0 | PLATED | NON-PLATED | DRILL CHART: TOP to BOTTOM | ALL UNITS ARE IN MILS | QTY | 174 | 23 | 6 | 4 | TOLERANCE/NOTES
